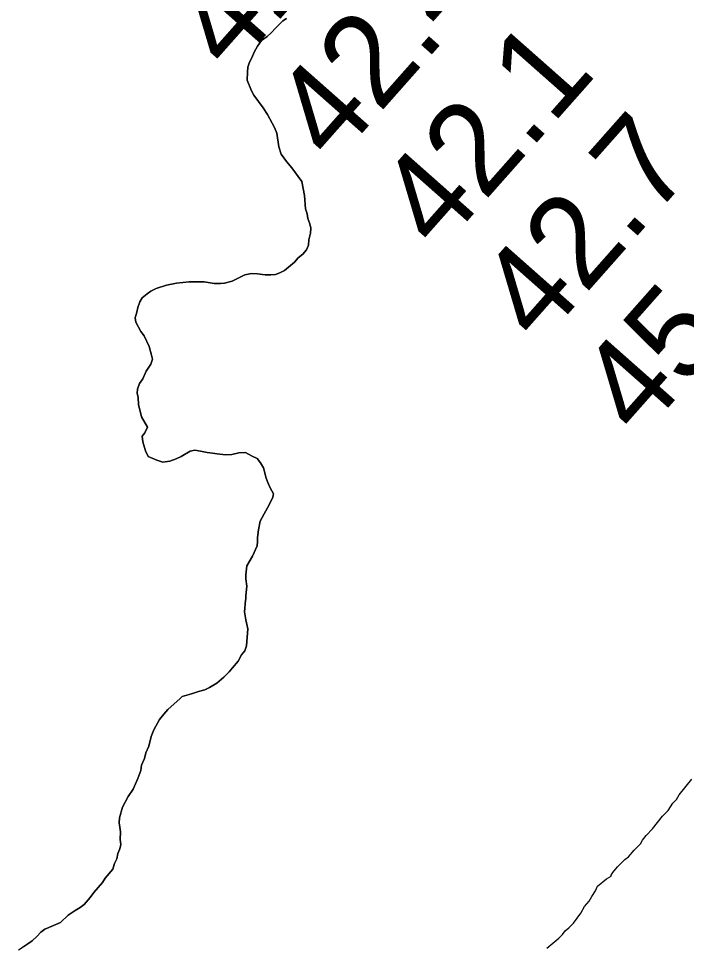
# Model space of a CAD drawing. Extents: x 3172297 to 3210190, y 958463 to 983887.
# Drawn here: x 3191406 to 3191893, y 965104 to 965781 of the extents above; entities that cross this region are included whole.
import ezdxf

# ---------------------------------------------------------------- set-up
doc = ezdxf.new("R2010")
doc.units = 0
for name, color, linetype in [('V-RIVR-RANG', 7, 'Continuous'), ('V-SITE-VEGE', 7, 'Continuous'), ('V-TOPO-SHOR', 7, 'Continuous'), ('V-WETL-SWMP', 7, 'Continuous')]:
    doc.layers.add(name, color=color, linetype=linetype)

msp = doc.modelspace()

# ---------------------------------------------------------------- linework, layer by layer
at = {"layer": 'V-SITE-VEGE'}
for p, q in [((3191598.67, 965779.53), (3191593.86, 965774.69)), ((3191601.42, 965781.26), (3191598.67, 965779.53)), ((3191590.08, 965770.55), (3191587.34, 965768.13)), ((3191593.86, 965774.69), (3191590.08, 965770.55)), ((3191583.21, 965765.36), (3191580.13, 965761.21)), ((3191587.34, 965768.13), (3191583.21, 965765.36)), ((3191577.73, 965756.73), (3191576.02, 965752.59)), ((3191580.13, 965761.21), (3191577.73, 965756.73)), ((3191574.31, 965749.48), (3191573.29, 965745.69)), ((3191576.02, 965752.59), (3191574.31, 965749.48)), ((3191572.95, 965742.24), (3191572.63, 965736.39)), ((3191573.29, 965745.69), (3191572.95, 965742.24)), ((3191572.63, 965736.39), (3191575.76, 965728.48)), ((3191575.76, 965728.48), (3191577.49, 965725.38)), ((3191577.49, 965725.38), (3191584.41, 965716.11)), ((3191584.41, 965716.11), (3191587.52, 965711.29)), ((3191587.52, 965711.29), (3191592.72, 965701.67)), ((3191592.72, 965701.67), (3191594.46, 965697.54)), ((3191594.46, 965697.54), (3191595.87, 965687.55)), ((3191595.87, 965687.55), (3191597.6, 965682.39)), ((3191597.6, 965682.39), (3191601.41, 965676.89)), ((3191601.41, 965676.89), (3191605.21, 965672.43)), ((3191605.21, 965672.43), (3191612.48, 965662.46)), ((3191612.48, 965662.46), (3191614.58, 965652.14)), ((3191614.58, 965652.14), (3191615.3, 965642.49)), ((3191615.3, 965642.49), (3191616.35, 965638.71)), ((3191616.35, 965638.71), (3191617.04, 965635.27)), ((3191617.04, 965635.27), (3191618.44, 965631.48)), ((3191618.44, 965631.48), (3191619.13, 965628.39)), ((3191619.13, 965628.39), (3191618.8, 965624.6)), ((3191617.79, 965619.77), (3191617.45, 965615.98)), ((3191618.8, 965624.6), (3191617.79, 965619.77)), ((3191617.45, 965615.98), (3191616.09, 965612.53)), ((3191609.91, 965606.66), (3191607.16, 965603.55)), ((3191613.34, 965609.42), (3191609.91, 965606.66)), ((3191616.09, 965612.53), (3191613.34, 965609.42)), ((3191607.16, 965603.55), (3191599.95, 965597.32)), ((3191571.02, 965594.13), (3191561.74, 965589.62)), ((3191575.84, 965595.18), (3191571.02, 965594.13)), ((3191580.32, 965594.85), (3191575.84, 965595.18)), ((3191585.84, 965594.18), (3191580.32, 965594.85)), ((3191589.97, 965594.19), (3191585.84, 965594.18)), ((3191593.41, 965594.55), (3191589.97, 965594.19)), ((3191596.51, 965595.59), (3191593.41, 965594.55)), ((3191599.95, 965597.32), (3191596.51, 965595.59)), ((3191513.87, 965586.71), (3191506.3, 965584.28)), ((3191521.1, 965588.11), (3191513.87, 965586.71)), ((3191530.4, 965589.18), (3191521.1, 965588.11)), ((3191541.42, 965589.21), (3191530.4, 965589.18)), ((3191548.66, 965587.86), (3191541.42, 965589.21)), ((3191553.13, 965587.87), (3191548.66, 965587.86)), ((3191556.23, 965588.22), (3191553.13, 965587.87)), ((3191561.74, 965589.62), (3191556.23, 965588.22)), ((3191499.77, 965580.46), (3191495.99, 965577.35)), ((3191502.52, 965582.2), (3191499.77, 965580.46)), ((3191506.3, 965584.28), (3191502.52, 965582.2)), ((3191494.28, 965574.59), (3191492.91, 965570.45)), ((3191495.99, 965577.35), (3191494.28, 965574.59)), ((3191492.23, 965567.01), (3191490.87, 965562.87)), ((3191492.91, 965570.45), (3191492.23, 965567.01)), ((3191490.87, 965562.87), (3191491.57, 965559.77)), ((3191491.57, 965559.77), (3191495.04, 965552.89)), ((3191495.04, 965552.89), (3191497.46, 965549.8)), ((3191497.46, 965549.8), (3191501.27, 965541.89)), ((3191501.27, 965541.89), (3191503.02, 965535.7)), ((3191503.71, 965532.6), (3191502.35, 965529.15)), ((3191503.02, 965535.7), (3191503.71, 965532.6)), ((3191502.35, 965529.15), (3191498.92, 965523.97)), ((3191496.53, 965518.45), (3191494.13, 965515)), ((3191498.92, 965523.97), (3191496.53, 965518.45)), ((3191494.13, 965515), (3191492.76, 965510.86)), ((3191492.76, 965510.86), (3191492.43, 965507.76)), ((3191492.43, 965507.76), (3191493.13, 965504.67)), ((3191493.13, 965504.67), (3191493.49, 965499.5)), ((3191493.49, 965499.5), (3191495.58, 965490.55)), ((3191495.58, 965490.55), (3191500.09, 965482.99)), ((3191498.03, 965478.85), (3191495.97, 965476.43)), ((3191500.09, 965482.99), (3191498.03, 965478.85)), ((3191495.97, 965476.43), (3191496.68, 965472.3)), ((3191496.68, 965472.3), (3191498.42, 965465.76)), ((3191498.42, 965465.76), (3191500.5, 965461.63)), ((3191524.61, 965461.71), (3191531.14, 965465.52)), ((3191531.14, 965465.52), (3191534.58, 965466.22)), ((3191534.58, 965466.22), (3191538.72, 965465.55)), ((3191538.72, 965465.55), (3191543.55, 965464.53)), ((3191543.55, 965464.53), (3191547.34, 965464.2)), ((3191547.34, 965464.2), (3191550.78, 965463.52)), ((3191561.46, 965463.21), (3191566.62, 965464.26)), ((3191566.62, 965464.26), (3191571.45, 965464.62)), ((3191571.45, 965464.62), (3191576.28, 965461.88)), ((3191500.5, 965461.63), (3191506.71, 965458.9)), ((3191506.71, 965458.9), (3191511.19, 965457.53)), ((3191511.19, 965457.53), (3191516.36, 965458.24)), ((3191516.36, 965458.24), (3191520.83, 965459.98)), ((3191520.83, 965459.98), (3191524.61, 965461.71)), ((3191550.78, 965463.52), (3191556.99, 965462.85)), ((3191556.99, 965462.85), (3191561.46, 965463.21)), ((3191576.28, 965461.88), (3191580.07, 965460.17)), ((3191580.07, 965460.17), (3191582.49, 965457.08)), ((3191582.49, 965457.08), (3191584.57, 965453.3)), ((3191584.57, 965453.3), (3191586.66, 965445.73)), ((3191586.66, 965445.73), (3191587.71, 965442.63)), ((3191587.71, 965442.63), (3191589.44, 965438.84)), ((3191589.44, 965438.84), (3191591.87, 965434.38)), ((3191591.53, 965431.96), (3191588.79, 965426.44)), ((3191591.87, 965434.38), (3191591.53, 965431.96)), ((3191588.79, 965426.44), (3191585.02, 965419.89)), ((3191585.02, 965419.89), (3191582.29, 965414.37)), ((3191582.29, 965414.37), (3191580.93, 965408.16)), ((3191580.93, 965408.16), (3191580.26, 965402.65)), ((3191579.93, 965396.45), (3191576.51, 965388.86)), ((3191580.27, 965399.55), (3191579.93, 965396.45)), ((3191580.26, 965402.65), (3191580.27, 965399.55)), ((3191576.51, 965388.86), (3191572.41, 965381.96)), ((3191572.41, 965381.96), (3191571.74, 965375.41)), ((3191571.74, 965375.41), (3191571.75, 965372.31)), ((3191571.75, 965372.31), (3191572.45, 965367.15)), ((3191572.45, 965367.15), (3191571.79, 965359.91)), ((3191571.45, 965356.47), (3191570.79, 965348.2)), ((3191571.79, 965357.84), (3191571.45, 965356.47)), ((3191571.79, 965359.91), (3191571.79, 965357.84)), ((3191570.79, 965348.2), (3191571.84, 965342.34)), ((3191571.84, 965342.34), (3191573.24, 965335.8)), ((3191573.24, 965335.8), (3191572.25, 965323.4)), ((3191572.25, 965323.4), (3191570.88, 965319.95)), ((3191568.48, 965316.84), (3191566.08, 965312.36)), ((3191570.88, 965319.95), (3191568.48, 965316.84)), ((3191566.08, 965312.36), (3191561.97, 965307.52)), ((3191559.57, 965304.42), (3191555.79, 965300.61)), ((3191561.97, 965307.52), (3191559.57, 965304.42)), ((3191550.64, 965296.12), (3191545.14, 965293)), ((3191555.79, 965300.61), (3191550.64, 965296.12)), ((3191532.06, 965288.48), (3191526.9, 965287.09)), ((3191537.22, 965290.22), (3191532.06, 965288.48)), ((3191541.7, 965291.27), (3191537.22, 965290.22)), ((3191545.14, 965293), (3191541.7, 965291.27)), ((3191523.81, 965285.01), (3191514.88, 965277.06)), ((3191525.18, 965286.39), (3191523.81, 965285.01)), ((3191526.9, 965287.09), (3191525.18, 965286.39)), ((3191514.88, 965277.06), (3191511.79, 965273.61)), ((3191508.7, 965269.81), (3191504.59, 965262.21)), ((3191511.79, 965273.61), (3191508.7, 965269.81)), ((3191504.59, 965262.21), (3191502.54, 965257.39)), ((3191502.54, 965257.39), (3191500.84, 965250.15)), ((3191500.84, 965250.15), (3191498.79, 965245.32)), ((3191497.77, 965241.18), (3191495.72, 965236.35)), ((3191498.79, 965245.32), (3191497.77, 965241.18)), ((3191495.72, 965236.35), (3191495.04, 965232.56)), ((3191495.04, 965232.56), (3191493, 965226.7)), ((3191493, 965226.7), (3191489.58, 965218.77)), ((3191485.8, 965213.59), (3191481.7, 965205.65)), ((3191489.58, 965218.77), (3191485.8, 965213.59)), ((3191481.7, 965205.65), (3191479.66, 965198.07)), ((3191479.66, 965198.07), (3191479.32, 965194.28)), ((3191479.32, 965194.28), (3191479.68, 965191.18)), ((3191479.68, 965191.18), (3191480.38, 965187.74)), ((3191480.38, 965187.74), (3191480.05, 965182.22)), ((3191480.05, 965182.22), (3191480.41, 965178.44)), ((3191479.73, 965175.33), (3191478.36, 965171.88)), ((3191480.41, 965178.44), (3191479.73, 965175.33)), ((3191477.69, 965168.09), (3191475.98, 965164.64)), ((3191478.36, 965171.88), (3191477.69, 965168.09)), ((3191474.61, 965160.51), (3191469.12, 965153.95)), ((3191475.98, 965164.64), (3191474.61, 965160.51)), ((3191469.12, 965153.95), (3191467.07, 965150.84)), ((3191467.07, 965150.84), (3191460.89, 965143.58)), ((3191458.15, 965139.79), (3191453.69, 965134.61)), ((3191460.89, 965143.58), (3191458.15, 965139.79)), ((3191450.94, 965132.53), (3191447.15, 965130.45)), ((3191453.69, 965134.61), (3191450.94, 965132.53)), ((3191442, 965126.99), (3191436.51, 965121.46)), ((3191447.15, 965130.45), (3191442, 965126.99)), ((3191436.51, 965121.46), (3191427.91, 965117.99)), ((3191422.06, 965114.53), (3191419.31, 965111.42)), ((3191425.15, 965116.6), (3191422.06, 965114.53)), ((3191427.91, 965117.99), (3191425.15, 965116.6)), ((3191412.79, 965105.89), (3191409.01, 965103.6)), ((3191415.88, 965108.31), (3191412.79, 965105.89)), ((3191419.31, 965111.42), (3191415.88, 965108.31))]:
    msp.add_line(p, q, dxfattribs=at)
at = {"layer": 'V-TOPO-SHOR'}
for points in [[(3191495.58, 965490.55), (3191493.49, 965499.5), (3191493.13, 965504.67), (3191492.43, 965507.76), (3191492.76, 965510.86), (3191494.13, 965515), (3191496.53, 965518.45), (3191498.92, 965523.97), (3191502.35, 965529.15), (3191503.71, 965532.6), (3191503.02, 965535.7), (3191501.27, 965541.89), (3191497.46, 965549.8), (3191495.04, 965552.89), (3191491.57, 965559.77), (3191490.87, 965562.87), (3191492.23, 965567.01), (3191492.91, 965570.45), (3191494.28, 965574.59), (3191495.99, 965577.35), (3191499.77, 965580.46), (3191502.52, 965582.2), (3191506.3, 965584.28), (3191513.87, 965586.71), (3191521.1, 965588.11), (3191530.4, 965589.18), (3191541.42, 965589.21), (3191548.66, 965587.86), (3191553.13, 965587.87), (3191556.23, 965588.22), (3191561.74, 965589.62), (3191571.02, 965594.13), (3191575.84, 965595.18), (3191580.32, 965594.85), (3191585.84, 965594.18), (3191589.97, 965594.19), (3191593.41, 965594.55), (3191596.51, 965595.59), (3191599.95, 965597.32), (3191607.16, 965603.55), (3191609.91, 965606.66), (3191613.34, 965609.42), (3191616.09, 965612.53), (3191617.45, 965615.98), (3191617.79, 965619.77), (3191618.8, 965624.6), (3191619.13, 965628.39), (3191618.44, 965631.48), (3191617.04, 965635.27), (3191616.35, 965638.71), (3191615.3, 965642.49), (3191614.58, 965652.14), (3191612.48, 965662.46), (3191605.21, 965672.43), (3191601.41, 965676.89), (3191597.6, 965682.39), (3191595.87, 965687.55), (3191594.46, 965697.54), (3191592.72, 965701.67), (3191587.52, 965711.29), (3191584.41, 965716.11), (3191577.49, 965725.38), (3191575.76, 965728.48), (3191572.63, 965736.39), (3191572.95, 965742.24), (3191573.29, 965745.69), (3191574.31, 965749.48), (3191576.02, 965752.59), (3191577.73, 965756.73), (3191580.13, 965761.21), (3191583.21, 965765.36), (3191587.34, 965768.13), (3191590.08, 965770.55), (3191593.86, 965774.69), (3191598.67, 965779.53), (3191601.42, 965781.26)], [(3191422.06, 965114.53), (3191425.15, 965116.6), (3191427.91, 965117.99), (3191436.51, 965121.46), (3191442, 965126.99), (3191447.15, 965130.45), (3191450.94, 965132.53), (3191453.69, 965134.61), (3191458.15, 965139.79), (3191460.89, 965143.58), (3191467.07, 965150.84), (3191469.12, 965153.95), (3191474.61, 965160.51), (3191475.98, 965164.64), (3191477.69, 965168.09), (3191478.36, 965171.88), (3191479.73, 965175.33), (3191480.41, 965178.44), (3191480.05, 965182.22), (3191480.38, 965187.74), (3191479.68, 965191.18), (3191479.32, 965194.28), (3191479.66, 965198.07), (3191481.7, 965205.65), (3191485.81, 965213.59), (3191489.58, 965218.77), (3191493, 965226.7), (3191495.04, 965232.56), (3191495.72, 965236.35), (3191497.77, 965241.18), (3191498.79, 965245.32), (3191500.84, 965250.15), (3191502.54, 965257.39), (3191504.59, 965262.21), (3191508.7, 965269.81), (3191511.79, 965273.61), (3191514.88, 965277.06), (3191523.81, 965285.01), (3191525.18, 965286.39), (3191526.9, 965287.09), (3191532.06, 965288.48), (3191537.22, 965290.22), (3191541.7, 965291.27), (3191545.14, 965293), (3191550.64, 965296.12), (3191555.79, 965300.61), (3191559.57, 965304.42), (3191561.97, 965307.52), (3191566.08, 965312.36), (3191568.48, 965316.84), (3191570.88, 965319.95), (3191572.25, 965323.4), (3191573.24, 965335.8), (3191571.84, 965342.34), (3191570.79, 965348.2), (3191571.45, 965356.47), (3191571.79, 965357.84), (3191571.79, 965359.91), (3191572.45, 965367.15), (3191571.75, 965372.31), (3191571.74, 965375.41), (3191572.4, 965381.96), (3191576.51, 965388.86), (3191579.93, 965396.45), (3191580.27, 965399.55), (3191580.26, 965402.65), (3191580.93, 965408.16), (3191582.29, 965414.37), (3191585.02, 965419.89), (3191588.79, 965426.44), (3191591.53, 965431.96), (3191591.87, 965434.38), (3191589.44, 965438.84), (3191587.71, 965442.63), (3191586.66, 965445.73), (3191584.57, 965453.3), (3191582.49, 965457.08), (3191580.07, 965460.17), (3191576.28, 965461.88), (3191571.45, 965464.62), (3191566.62, 965464.26), (3191561.46, 965463.21), (3191556.99, 965462.85), (3191550.78, 965463.52), (3191547.34, 965464.2), (3191543.55, 965464.53), (3191538.72, 965465.55), (3191534.58, 965466.22), (3191531.14, 965465.52), (3191524.61, 965461.71), (3191520.83, 965459.98), (3191516.36, 965458.24), (3191511.19, 965457.53), (3191506.71, 965458.9), (3191500.5, 965461.63), (3191498.42, 965465.76), (3191496.68, 965472.3), (3191495.97, 965476.43), (3191498.03, 965478.85), (3191500.09, 965482.99), (3191495.58, 965490.55)], [(3191405.91, 965101.73), (3191412.79, 965105.89), (3191415.88, 965108.31), (3191419.31, 965111.42), (3191422.06, 965114.53)]]:
    msp.add_lwpolyline(points, dxfattribs=at)
at = {"layer": 'V-WETL-SWMP'}
msp.add_lwpolyline([(3191791.32, 965102.8), (3191800.04, 965110.23), (3191802.72, 965112.93), (3191804.73, 965115.62), (3191807.42, 965117.65), (3191810.77, 965121.03), (3191816.13, 965128.44), (3191818.81, 965133.16), (3191822.16, 965137.21), (3191824.16, 965140.58), (3191826.84, 965144.63), (3191828.18, 965147.99), (3191834.89, 965153.4), (3191838.25, 965155.43), (3191838.24, 965156.1), (3191839.58, 965158.12), (3191842.93, 965162.17), (3191848.3, 965167.57), (3191850.98, 965169.6), (3191855, 965174.32), (3191859.7, 965179.05), (3191861.04, 965181.74), (3191863.71, 965185.11), (3191868.41, 965189.84), (3191875.78, 965199.28), (3191879.8, 965203.33), (3191883.15, 965208.72), (3191885.83, 965211.43), (3191887.84, 965214.8), (3191897.22, 965226.26)], dxfattribs=at)

# ---------------------------------------------------------------- texts
at = {"layer": 'V-RIVR-RANG'}
for s, p in [('42.3', (3191560.95, 965740.41)), ('42.4', (3191636.01, 965674.33)), ('42.1', (3191712.64, 965610.03)), ('42.7', (3191786.12, 965542.18)), ('45.0', (3191859.26, 965473.93))]:
    msp.add_text(s, height=67, rotation=48.49833, dxfattribs=at).set_placement(p)

doc.saveas('drawing.dxf')
